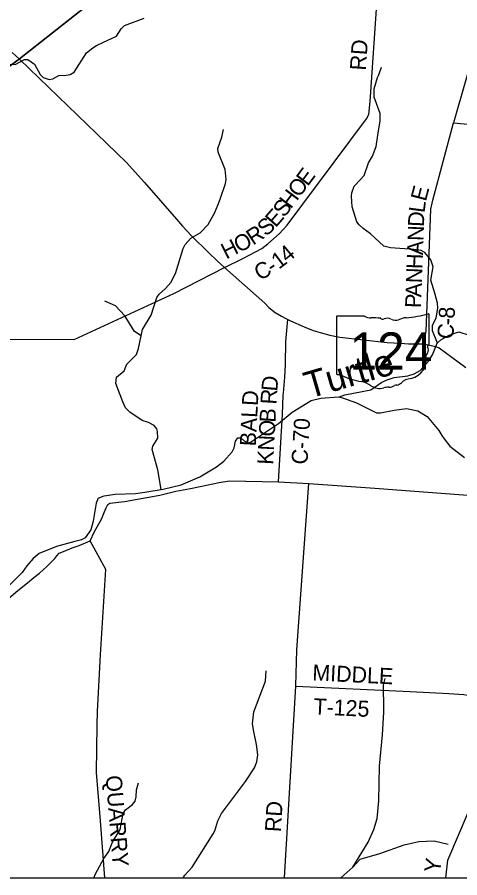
# Model space of a CAD drawing. Extents: x 0 to 48.6, y 0 to 22.
# Drawn here: x 5.519 to 7.09, y 14.1 to 17.154 of the extents above; entities that cross this region are included whole.
import ezdxf

# ---------------------------------------------------------------- set-up
doc = ezdxf.new("R2010")
doc.units = 0
for name, color, linetype in [('GM_X_Corporation', 7, 'Continuous'), ('GM_X_County_Road', 7, 'Continuous'), ('GM_X_County_Road_Text', 7, 'Continuous'), ('GM_X_Minor_River', 7, 'Continuous'), ('GM_X_Minor_River_Text', 7, 'Continuous'), ('GM_X_State_Location', 7, 'Continuous'), ('GM_X_State_Route', 7, 'Continuous'), ('GM_X_State_Shield', 7, 'Continuous'), ('GM_X_Township_Road', 7, 'Continuous'), ('GM_X_Township_Road_Text', 7, 'Continuous'), ('SH_Data', 7, 'Continuous')]:
    doc.layers.add(name, color=color, linetype=linetype)

msp = doc.modelspace()

# ---------------------------------------------------------------- linework, layer by layer
at = {"layer": 'GM_X_Corporation'}
msp.add_lwpolyline([(5.0944, 14.1), (8.9, 14.1), (8.9, 19.5692), (8.5348, 19.2897), (7.2261, 18.2847), (6.9471, 18.0777), (6.5365, 17.7727), (5.8387, 17.2541), (5.5264, 17.0064), (4.6225, 16.3345), (4.044, 15.9033), (4.0346, 15.8959), (4.0398, 15.887), (4.3544, 15.3539), (4.4679, 15.1616), (4.7542, 14.6766)], close=True, dxfattribs=at)
msp.add_lwpolyline([(4.6225, 16.3345), (5.5264, 17.0064), (5.8387, 17.2541)], dxfattribs=at)
msp.add_lwpolyline([(4.6225, 16.3345), (5.5264, 17.0064), (5.8387, 17.2541)], dxfattribs=at)
at = {"layer": 'GM_X_County_Road'}
msp.add_line((6.4462, 15.5059), (6.4531, 15.6249), dxfattribs=at)
for points in [[(6.2545, 16.2661), (6.3196, 16.2983), (6.3869, 16.3334), (6.4082, 16.3506), (6.4486, 16.3853), (6.4771, 16.4164), (6.644, 16.6404), (6.7584, 16.7938), (6.7668, 16.8095), (6.7711, 16.8557), (6.8142, 17.4789), (6.8183, 17.4898), (6.8434, 17.5207), (6.8575, 17.5377), (6.8672, 17.547), (6.9323, 17.5551), (7.0193, 17.5612), (7.1388, 17.5717)], [(7.2032, 17.2545), (7.0677, 16.7791)], [(6.9605, 15.9949), (6.9706, 16.0404), (6.9818, 16.3461), (6.9871, 16.4731), (6.9936, 16.5052), (7.0677, 16.7791), (7.7928, 16.7109), (7.9765, 16.6977), (8.7761, 16.6379), (8.7903, 16.6409)], [(4.6086, 15.1588), (4.64, 15.1582), (4.8348, 15.1585), (4.9035, 15.1586), (4.9331, 15.1596), (5.071, 15.181), (5.1203, 15.1895), (5.1743, 15.1992), (5.2077, 15.2059), (5.2218, 15.2088), (5.2271, 15.216), (5.2317, 15.2361), (5.2617, 15.7172), (5.2803, 16.0116), (5.7212, 16.011), (6.0742, 16.1743), (6.2545, 16.2661)], [(6.2545, 16.2661), (6.3972, 16.1396), (6.4122, 16.1243), (6.4349, 16.1067), (6.4568, 16.0932), (6.4724, 16.0848), (6.4788, 16.0816)], [(6.4633, 15.8135), (6.4636, 15.8205), (6.4689, 15.8772), (6.4716, 15.9216), (6.4726, 16.0032), (6.4788, 16.0816)], [(6.4788, 16.0816), (6.4894, 16.0763), (6.5371, 16.0554), (6.5689, 16.043), (6.5943, 16.0356), (6.6288, 16.0259), (6.6637, 16.0188), (6.8318, 15.9993), (6.8797, 15.997)], [(6.8797, 15.997), (6.9077, 15.9957), (6.9605, 15.9949)], [(6.4531, 15.6249), (6.4601, 15.7439), (6.4633, 15.8135)], [(5.4143, 15.0302), (5.5209, 15.1202), (5.5548, 15.1463), (5.578, 15.1659), (5.5978, 15.1814), (5.6241, 15.2052), (5.6523, 15.2327), (5.6588, 15.2426), (5.6676, 15.2517), (5.6832, 15.258), (5.7136, 15.2712), (5.739, 15.2794), (5.7778, 15.2963), (5.7934, 15.3296), (5.8177, 15.373), (5.8278, 15.3967), (5.8347, 15.4128), (5.8407, 15.4248), (5.8477, 15.4299), (5.8991, 15.435), (6.0252, 15.4578), (6.0814, 15.4719), (6.134, 15.4819), (6.1687, 15.4893), (6.2355, 15.5031), (6.2728, 15.5086), (6.4462, 15.5059), (6.5537, 15.4992), (6.7885, 15.4828), (7.1812, 15.4537)]]:
    msp.add_lwpolyline(points, dxfattribs=at)
at = {"layer": 'GM_X_Minor_River'}
msp.add_line((5.7908, 14.1), (5.7966, 14.1143), dxfattribs=at)
for points in [[(5.8225, 17.0642), (5.8709, 17.0874), (5.8876, 17.1133), (5.9, 17.1245), (5.9694, 17.1511)], [(5.4863, 16.9882), (5.5112, 16.9867), (5.544, 17.0038), (5.5562, 17.004), (5.5795, 16.9882), (5.5999, 16.9511), (5.6104, 16.9408), (5.6315, 16.9329), (5.6445, 16.9354), (5.6662, 16.9469), (5.6924, 16.9481), (5.7061, 16.9514), (5.721, 16.9595), (5.7644, 17.0277), (5.7866, 17.046), (5.8, 17.0542), (5.8225, 17.0642)], [(7.0104, 15.9979), (6.9934, 16.0409), (6.9934, 16.061), (7.0055, 16.0858), (7.0118, 16.1225), (7.0105, 16.1392), (7.0016, 16.1746), (6.9876, 16.2215), (6.9948, 16.2688), (6.9872, 16.2936), (6.9652, 16.3197), (6.9532, 16.3264), (6.9263, 16.3302), (6.8434, 16.3353), (6.82, 16.3413), (6.7733, 16.3857), (6.747, 16.4047), (6.7332, 16.417), (6.7246, 16.4282), (6.7077, 16.4819), (6.7049, 16.5191), (6.7062, 16.5316), (6.7145, 16.555), (6.7365, 16.577), (6.7504, 16.5927), (6.7663, 16.638), (6.7799, 16.6613), (6.7926, 16.6956), (6.8014, 16.7516), (6.8069, 16.7857), (6.8077, 16.813), (6.7859, 16.871), (6.7863, 16.8998), (6.798, 16.9406), (6.8019, 16.9504), (6.8114, 16.9768)], [(6.0299, 15.4782), (6.018, 15.5483), (5.9975, 15.6199), (6.0003, 15.6324), (6.0175, 15.6602), (6.0171, 15.6837), (6.0138, 15.6936), (6.0049, 15.7051), (5.9842, 15.7161), (5.962, 15.7232), (5.9181, 15.7524), (5.9035, 15.7678), (5.8936, 15.7892), (5.8689, 15.8544), (5.8715, 15.8764), (5.8988, 15.8991), (5.9075, 15.9228), (5.9422, 15.9572), (5.9461, 15.9677), (5.9489, 15.9791), (5.9633, 16.0456), (5.9944, 16.0967), (6.0147, 16.1593), (6.0229, 16.171), (6.0456, 16.1911), (6.0637, 16.2128), (6.0809, 16.2452), (6.1081, 16.3335), (6.1144, 16.3482), (6.1352, 16.3699), (6.1685, 16.3887), (6.1967, 16.4182), (6.2205, 16.4614), (6.2355, 16.4995), (6.2399, 16.512), (6.2578, 16.5644), (6.2606, 16.578), (6.257, 16.6133), (6.2318, 16.6759), (6.2305, 16.6885), (6.2448, 16.7281), (6.2509, 16.756)], [(5.9586, 16.0239), (5.9355, 16.0385), (5.9003, 16.0948), (5.8672, 16.1302), (5.8299, 16.1467)], [(6.6627, 15.8067), (6.6823, 15.814), (6.774, 15.8315), (6.8135, 15.859), (6.8326, 15.8678), (6.857, 15.8754), (6.9056, 15.8818), (6.9281, 15.8887), (6.9487, 15.9009), (6.9785, 15.9338), (6.9925, 15.9563), (7.0094, 15.997), (7.0225, 16.0093), (7.0527, 16.0256), (7.0866, 16.0375), (7.1232, 16.0256)], [(5.8065, 15.4469), (5.8273, 15.4557), (5.8661, 15.4619), (5.9385, 15.4634), (5.9716, 15.4686), (6.037, 15.4793), (6.1002, 15.495), (6.1673, 15.5236), (6.2259, 15.5583), (6.2524, 15.5784), (6.2821, 15.6117), (6.2892, 15.626), (6.2933, 15.6502), (6.3015, 15.661), (6.3125, 15.6616), (6.3241, 15.6512), (6.3372, 15.6442), (6.3471, 15.6467), (6.4464, 15.7123), (6.4944, 15.7525), (6.5618, 15.7939), (6.5964, 15.8025), (6.6598, 15.8075), (6.6734, 15.8035), (6.7232, 15.7861), (6.7943, 15.7504), (6.8087, 15.7502), (6.857, 15.7593), (6.9011, 15.7658), (6.9412, 15.7573), (6.9738, 15.737), (7.0159, 15.6871), (7.0266, 15.6694), (7.034, 15.6576), (7.0544, 15.6315), (7.1069, 15.5912)], [(5.8065, 15.4469), (5.799, 15.4299), (5.7888, 15.3663), (5.78, 15.3345), (5.7595, 15.3067), (5.7469, 15.2997), (5.7237, 15.2935), (5.6575, 15.2761), (5.5961, 15.2514), (5.5754, 15.2334), (5.5526, 15.2071), (5.5356, 15.1834), (5.4922, 15.1396), (5.4501, 15.1097), (5.4282, 15.0865), (5.4191, 15.0301), (5.4185, 15.0145), (5.4221, 14.9644), (5.4296, 14.932)], [(6.1073, 14.1), (6.1137, 14.1091), (6.1394, 14.1372), (6.2147, 14.2557), (6.2202, 14.267), (6.2308, 14.3025), (6.2436, 14.3277), (6.3291, 14.4419), (6.3611, 14.4897), (6.3697, 14.5116), (6.3727, 14.5362), (6.3686, 14.5734), (6.3583, 14.619), (6.3544, 14.6464), (6.3584, 14.6892), (6.3995, 14.7975), (6.403, 14.8343)], [(6.6672, 14.1), (6.7099, 14.1373), (6.764, 14.2269), (6.7847, 14.2713), (6.7961, 14.3103), (6.8022, 14.3728), (6.805, 14.4956), (6.8159, 14.607), (6.8199, 14.6877), (6.8205, 14.6998), (6.8193, 14.7833), (6.8249, 14.8079)], [(5.7966, 14.1143), (5.8262, 14.169), (5.8435, 14.193), (5.8568, 14.2259), (5.8846, 14.2714), (5.8952, 14.3281), (5.9033, 14.3406), (5.9274, 14.36), (5.9374, 14.3723), (5.9414, 14.3878), (5.9417, 14.4121), (5.9488, 14.4367)], [(6.7099, 14.1373), (6.7364, 14.1658), (6.8059, 14.1865), (6.8918, 14.2168), (6.9441, 14.2287), (6.9983, 14.2306), (7.0484, 14.2193)]]:
    msp.add_lwpolyline(points, dxfattribs=at)
at = {"layer": 'GM_X_State_Route'}
for points in [[(5.5011, 17.0294), (5.5267, 17.0058)], [(5.5267, 17.0058), (5.8355, 16.7072), (5.874, 16.6708), (5.9053, 16.6394), (5.9702, 16.5683), (6.084, 16.4375), (6.1058, 16.413), (6.1379, 16.3786), (6.1978, 16.3193), (6.2299, 16.2887), (6.2545, 16.2661)], [(6.2545, 16.2661), (6.3972, 16.1396), (6.4122, 16.1243), (6.4349, 16.1067), (6.4568, 16.0932), (6.4724, 16.0848), (6.4788, 16.0816)], [(6.4788, 16.0816), (6.4894, 16.0763), (6.5371, 16.0554), (6.5689, 16.043), (6.5943, 16.0356), (6.6288, 16.0259), (6.6637, 16.0188), (6.8318, 15.9993), (6.8797, 15.997)], [(6.8797, 15.997), (6.9077, 15.9957), (6.9605, 15.9949)], [(6.9605, 15.9949), (6.9886, 15.989), (7.0041, 15.9858), (7.0166, 15.9804), (7.0839, 15.9313), (7.1108, 15.9106)]]:
    msp.add_lwpolyline(points, dxfattribs=at)
at = {"layer": 'GM_X_State_Shield'}
for p, q in [((6.9814, 15.9935), (6.9814, 16.0982)), ((6.6518, 16.0898), (6.6518, 15.8897)), ((6.7516, 16.0932), (6.655, 16.0932)), ((6.9813, 15.9935), (6.9814, 15.9935))]:
    msp.add_line(p, q, dxfattribs=at)
for centre, major_axis, start_param, end_param in [((6.864, 16.3661), (0.3495, 0), 4.814394, 5.042369), ((6.9777, 16.0986), (0.00367, 0), 6.141152, 7.989035), ((6.6556, 16.0902), (0.00382, 0), 1.712693, 3.28349), ((6.7745, 16.1165), (0.037, 0), 4.042523, 4.731795), ((6.7868, 15.9809), (0.133, 0), 1.404758, 1.657858), ((6.817, 16.0913), (0.0107, 0), 3.836095, 5.185415), ((6.8327, 16.0681), (0.0222, 0), 0.950623, 2.079405), ((6.8614, 16.0999), (0.0267, 0), 4.081561, 5.145723), ((6.9086, 16.0321), (0.0703, 0), 1.699011, 2.107814), ((6.9805, 15.9858), (0.00568, 0), 1.883978, 3.671073), ((6.9444, 15.9726), (0.0341, 0), 5.934695, 6.695948), ((6.9775, 15.9931), (0.00393, 0), 5.05454, 6.418171), ((6.8836, 15.9364), (0.0874, 0), 5.101752, 6.440018), ((6.9945, 15.9497), (0.0248, 0), 2.387724, 3.262537), ((6.6556, 15.8892), (0.00385, 0), 3.00124, 4.508301), ((6.6562, 15.9097), (0.0294, 0), 4.665946, 4.897461), ((6.6622, 15.8781), (0.0106, 0), 0.519207, 1.627899), ((6.796, 16.0579), (0.2524, 0), 4.195997, 4.488961), ((6.7208, 15.7998), (0.079, 0), 0.823519, 1.323587), ((6.8598, 15.8703), (0.0282, 0), 4.937069, 5.64225), ((6.9204, 15.8335), (0.0479, 0), 1.647645, 2.488434), ((6.8062, 15.8771), (0.0501, 0), 4.026481, 4.996735), ((6.8351, 15.808), (0.0412, 0), 1.495662, 1.94098), ((6.8388, 15.8622), (0.0267, 0), 4.691044, 5.507374), ((6.863, 15.8428), (0.00752, 0), 1.147584, 2.315152)]:
    msp.add_ellipse(centre, major_axis=major_axis, ratio=0.8, start_param=start_param, end_param=end_param, dxfattribs=at)
at = {"layer": 'GM_X_Township_Road'}
for points in [[(6.4677, 14.1), (6.5079, 14.7806), (6.508, 14.7818), (6.5117, 14.9086), (6.5537, 15.4992)], [(5.8028, 14.6414), (5.8035, 14.6897), (5.8142, 14.8919), (5.8332, 15.1937), (5.7778, 15.2963)], [(7.0398, 14.1), (7.0477, 14.1622), (7.268, 14.6779), (7.2906, 14.9021), (7.2983, 14.9038), (7.6625, 14.8205), (7.6772, 14.8167), (7.6879, 14.8187), (7.6911, 14.8254), (7.6578, 14.9749), (7.6622, 14.9831), (7.6738, 14.9885), (8.1804, 15.1061)], [(6.5079, 14.7806), (6.9133, 14.7616), (7.0509, 14.7543), (7.104, 14.7505), (7.1301, 14.746), (7.268, 14.6779)], [(5.8302, 14.1), (5.814, 14.3019), (5.8004, 14.474), (5.8028, 14.6414)]]:
    msp.add_lwpolyline(points, dxfattribs=at)
at = {"layer": 'SH_Data'}
msp.add_line((2.1, 14.1), (8.9, 14.1), dxfattribs=at)

# ---------------------------------------------------------------- texts
at = {"layer": 'GM_X_County_Road_Text'}
for s, height, rotation, p in [('RD', 0.05682, 86.0551, (6.7562, 16.9639)), ('E', 0.0568, 53.2694, (6.5498, 16.5517)), ('O', 0.0568, 53.2671, (6.5199, 16.5116)), ('E', 0.0568, 75.5324, (6.9695, 16.4984)), ('H', 0.0568, 53.2671, (6.49, 16.4715)), ('S', 0.0568, 53.0185, (6.4668, 16.4407)), ('L', 0.0568, 82.5475, (6.9644, 16.4581)), ('E', 0.0568, 48.9574, (6.4361, 16.4052)), ('S', 0.0568, 41.1384, (6.4013, 16.374)), ('D', 0.0568, 87.6626, (6.9624, 16.4095)), ('R', 0.0568, 33.4369, (6.3557, 16.3433)), ('N', 0.0568, 87.9669, (6.9607, 16.3596)), ('O', 0.0568, 27.2497, (6.3055, 16.317)), ('H', 0.0568, 26.8786, (6.2605, 16.2942)), ('4', 0.0568, 39.5722, (6.4778, 16.2808)), ('A', 0.0568, 87.9669, (6.9589, 16.3096)), ('1', 0.0568, 36.7845, (6.4474, 16.258)), ('H', 0.0568, 87.9669, (6.9571, 16.2597)), ('C', 0.0568, 28.2043, (6.379, 16.2181)), ('-', 0.0568, 33.4947, (6.425, 16.2431)), ('N', 0.0568, 87.9669, (6.9554, 16.2097)), ('A', 0.0568, 87.9677, (6.9536, 16.1597)), ('P', 0.0568, 87.9659, (6.9522, 16.1214)), ('8', 0.0568, 87.9014, (7.0713, 16.0836)), ('-', 0.0568, 87.7326, (7.0704, 16.0601)), ('C', 0.0568, 83.79, (7.065, 16.0094)), ('D', 0.0568, 84.9995, (6.4416, 15.8249)), ('BALD', 0.05682, 86.9998, (6.3653, 15.6305)), ('R', 0.0568, 86.3952, (6.4386, 15.7787)), ('B', 0.0568, 86.9133, (6.4352, 15.7147)), ('O', 0.0568, 86.9272, (6.4325, 15.6648)), ('C-70', 0.05682, 86.5731, (6.5487, 15.5656)), ('N', 0.0568, 86.9258, (6.4298, 15.6149)), ('K', 0.0568, 86.9277, (6.4271, 15.565))]:
    msp.add_text(s, height=height, rotation=rotation, dxfattribs=at).set_placement(p)
at = {"layer": 'GM_X_Minor_River_Text'}
msp.add_text('Turtle', height=0.0947, rotation=16.1812, dxfattribs=at).set_placement((6.5536, 15.7998))
at = {"layer": 'GM_X_State_Location'}
for s in ['s', 'r']:
    msp.add_text(s, height=0.000189, dxfattribs=at).set_placement((6.8129, 15.9764))
msp.add_text('124', height=0.000189, rotation=0, dxfattribs=at).set_placement((6.746, 15.9627))
at = {"layer": 'GM_X_State_Shield'}
msp.add_text('124', height=0.13184, dxfattribs=at).set_placement((6.6983, 15.9038))
at = {"layer": 'GM_X_Township_Road_Text'}
for s, height, rotation, p in [('MIDDLE', 0.05682, 357.1731, (6.5654, 14.8007)), ('T-125', 0.05682, 357.1941, (6.5695, 14.6805)), ('QUARRY', 0.05682, 274.5609, (5.8326, 14.4615)), ('RD', 0.05682, 86.5168, (6.4546, 14.2612)), ('Y', 0.0568, 81.9284, (7.0191, 14.115))]:
    msp.add_text(s, height=height, rotation=rotation, dxfattribs=at).set_placement(p)

doc.saveas('drawing.dxf')
